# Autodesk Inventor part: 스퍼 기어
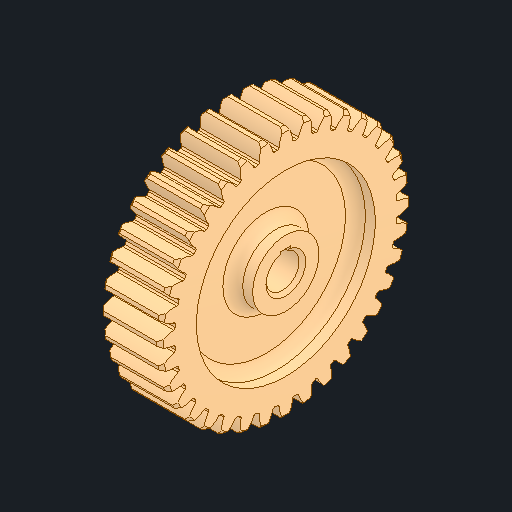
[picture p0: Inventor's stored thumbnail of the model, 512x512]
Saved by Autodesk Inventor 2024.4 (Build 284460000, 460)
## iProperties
Created: 2025-10
Part Number: 스퍼 기어
Material: 강철, 합금
Document SubType Name: Modeling
Designer: user
Density: 7.73 g/cm^3
Appearance: 기본값
Author: jhkim
Sending System: Autodesk Inventor 2026
Preprocessor: ST-DEVELOPER v20.1
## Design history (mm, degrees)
feature "솔리드1"
node "솔리드2"
